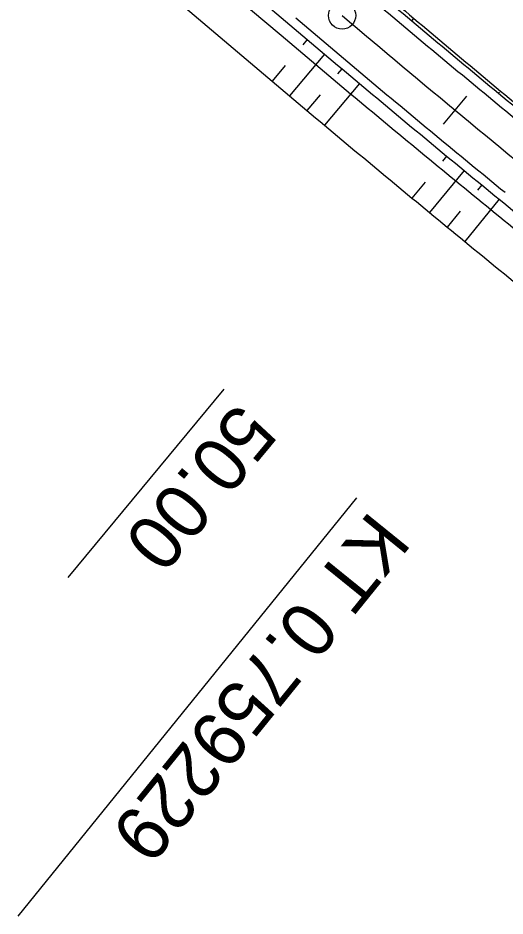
# Model space of a CAD drawing. Extents: x -481656 to -478728, y -1113199 to -1110710.
# Drawn here: x -481200.49 to -481173.62, y -1113146.51 to -1113096.94 of the extents above; entities that cross this region are included whole.
import ezdxf

# ---------------------------------------------------------------- set-up
doc = ezdxf.new("R2010")
doc.units = 0
for name, color, linetype in [('C11_HATCH_SLOPE_L', 7, 'Continuous'), ('C11_HATCH_SLOPE_R', 7, 'Continuous'), ('C11_HLBODY', 7, 'Continuous'), ('C11_HRANA_TELESO', 7, 'Continuous'), ('C11_KORUNA', 7, 'Continuous'), ('C11_OSA', 7, 'Continuous'), ('C11_PRIKOP', 7, 'Continuous'), ('C11_STANICENI', 7, 'Continuous'), ('C11_VOZOVKA', 7, 'Continuous'), ('C11_ZPEVKRAJ', 7, 'Continuous')]:
    doc.layers.add(name, color=color, linetype=linetype)

msp = doc.modelspace()

# ---------------------------------------------------------------- linework, layer by layer
at = {"layer": 'C11_HATCH_SLOPE_L'}
for p, q in [((-481178.764, -1113097.1), (-481178.644, -1113096.957)), ((-481173.974, -1113101.088), (-481173.924, -1113101.028)), ((-481173.874, -1113100.967), (-481173.874, -1113100.967))]:
    msp.add_line(p, q, dxfattribs=at)
at = {"layer": 'C11_HATCH_SLOPE_R'}
for p, q in [((-481184.53, -1113098.124), (-481184.774, -1113098.412)), ((-481183.574, -1113098.933), (-481185.513, -1113101.229)), ((-481185.744, -1113099.56), (-481186.471, -1113100.419)), ((-481182.616, -1113099.741), (-481182.857, -1113100.028)), ((-481181.656, -1113100.547), (-481183.588, -1113102.849)), ((-481183.825, -1113101.177), (-481184.551, -1113102.04)), ((-481176.84, -1113104.557), (-481177.075, -1113104.842)), ((-481175.873, -1113105.355), (-481177.782, -1113107.674)), ((-481178.031, -1113106), (-481178.752, -1113106.873)), ((-481174.904, -1113106.151), (-481175.137, -1113106.435)), ((-481173.935, -1113106.945), (-481175.839, -1113109.273)), ((-481176.09, -1113107.596), (-481176.811, -1113108.474))]:
    msp.add_line(p, q, dxfattribs=at)
at = {"layer": 'C11_HLBODY'}
msp.add_line((-481181.811, -1113123.42), (-481200.495, -1113146.507), dxfattribs=at)
msp.add_circle((-481182.61, -1113096.802), 0.75, dxfattribs=at)
at = {"layer": 'C11_HRANA_TELESO'}
msp.add_line((-481191.242, -1113096.382), (-481187.425, -1113099.612), dxfattribs=at)
for centre, radius, start, end in [((-479626.705, -1111275.844), 2392.69, 229.443117, 229.562619), ((-480662.911, -1112488.56), 797.576, 229.712358, 230.070464), ((-479627.561, -1111254.957), 2415.766, 229.7817, 229.900778), ((-480663.631, -1112487.93), 797.598, 230.139183, 230.497286), ((-480666.373, -1112485.661), 805.254, 230.036411, 230.394511), ((-480665.303, -1112486.546), 805.255, 230.295675, 230.653775), ((-480919.603, -1112798.704), 402.629, 230.47549, 231.19098)]:
    msp.add_arc(centre, radius, start, end, dxfattribs=at)
at = {"layer": 'C11_KORUNA'}
msp.add_line((-481189.302, -1113094.088), (-481185.485, -1113097.317), dxfattribs=at)
for centre, radius, start, end in [((-479637.316, -1111266.367), 2393.25, 229.783661, 229.903153), ((-479631.514, -1111259.487), 2406.75, 229.783933, 229.903175), ((-480665.956, -1112486.009), 797.75, 229.997717, 230.355817), ((-480665.956, -1112486.009), 797.75, 230.355817, 230.713917), ((-480665.956, -1112486.009), 802.25, 229.997717, 230.355817), ((-480665.956, -1112486.009), 802.25, 230.355817, 230.713917), ((-480918.954, -1112797.291), 401.125, 230.53069, 231.24658)]:
    msp.add_arc(centre, radius, start, end, dxfattribs=at)
at = {"layer": 'C11_OSA'}
msp.add_arc((-480665.956, -1112486.009), 800, 229.772939, 231.016817, dxfattribs=at)
at = {"layer": 'C11_PRIKOP'}
msp.add_line((-481189.795, -1113094.671), (-481185.972, -1113097.894), dxfattribs=at)
for centre, radius, start, end in [((-479633.34, -1111255.998), 2408.993, 229.870675, 229.989875), ((-480666.892, -1112485.229), 802.994, 230.084642, 230.442742), ((-480666.893, -1112485.238), 802.986, 230.442394, 230.800494), ((-480919.655, -1112797.189), 401.491, 230.61752, 231.33331)]:
    msp.add_arc(centre, radius, start, end, dxfattribs=at)
at = {"layer": 'C11_STANICENI'}
for p, q in [((-481177.008, -1113102.796), (-481175.732, -1113101.256)), ((-481189.13, -1113117.426), (-481197.744, -1113127.822))]:
    msp.add_line(p, q, dxfattribs=at)
at = {"layer": 'C11_VOZOVKA'}
for centre, radius, start, end in [((-479636.671, -1111265.603), 2394.75, 229.783692, 229.903156), ((-479632.159, -1111260.251), 2405.25, 229.783903, 229.903172), ((-480665.956, -1112486.009), 798.25, 229.997717, 230.355817), ((-480665.956, -1112486.009), 801.75, 229.997717, 230.355817), ((-480665.956, -1112486.009), 798.25, 230.355817, 230.713917), ((-480665.956, -1112486.009), 801.75, 230.355817, 230.713917)]:
    msp.add_arc(centre, radius, start, end, dxfattribs=at)
at = {"layer": 'C11_ZPEVKRAJ'}
for centre, radius, start, end in [((-479636.671, -1111265.603), 2394.75, 229.783692, 229.903156), ((-479632.159, -1111260.251), 2405.25, 229.783903, 229.903172), ((-480665.956, -1112486.009), 798.25, 229.997717, 230.355817), ((-480665.956, -1112486.009), 801.75, 229.997717, 230.355817), ((-480665.956, -1112486.009), 798.25, 230.355817, 230.713917), ((-480665.956, -1112486.009), 801.75, 230.355817, 230.713917)]:
    msp.add_arc(centre, radius, start, end, dxfattribs=at)

# ---------------------------------------------------------------- texts
at = {"layer": 'C11_HLBODY'}
msp.add_text('KT 0.759229', height=2.999, rotation=231.0168, dxfattribs=at).set_placement((-481181.033, -1113124.048))
at = {"layer": 'C11_STANICENI'}
msp.add_text('50.00', height=3, rotation=230.3558, dxfattribs=at).set_placement((-481188.36, -1113118.064))

doc.saveas('drawing.dxf')
